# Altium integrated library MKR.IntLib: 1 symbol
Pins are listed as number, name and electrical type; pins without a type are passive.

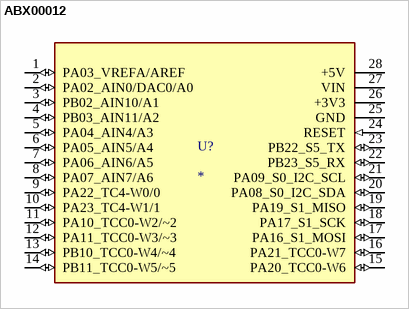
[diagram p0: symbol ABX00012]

## ABX00012
designator U?
Mkrzero Brd With Headers Mounted; MP: ABX00012
footprint ARDUINO_ABX00012
pins: 1 PA03_VREFA/AREF (io), 2 PA02_AIN0/DAC0/A0 (io), 3 PB02_AIN10/A1 (io), 4 PB03_AIN11/A2 (io), 5 PA04_AIN4/A3 (io), 6 PA05_AIN5/A4 (io), 7 PA06_AIN6/A5 (io), 8 PA07_AIN7/A6 (io), 9 PA22_TC4-W0/0 (io), 10 PA23_TC4-W1/1 (io), 11 PA10_TCC0-W2/~2 (io), 12 PA11_TCC0-W3/~3 (io), 13 PB10_TCC0-W4/~4 (io), 14 PB11_TCC0-W5/~5 (io), 15 PA20_TCC0-W6 (io), 16 PA21_TCC0-W7 (io), 17 PA16_S1_MOSI (io), 18 PA17_S1_SCK (io), 19 PA19_S1_MISO (io), 20 PA08_S0_I2C_SDA (io), 21 PA09_S0_I2C_SCL (io), 22 PB23_S5_RX (io), 23 PB22_S5_TX (io), 24 RESET (in), 25 GND (power), 26 +3V3 (power), 27 VIN (power), 28 +5V (power)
